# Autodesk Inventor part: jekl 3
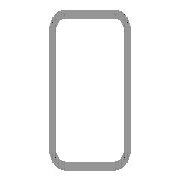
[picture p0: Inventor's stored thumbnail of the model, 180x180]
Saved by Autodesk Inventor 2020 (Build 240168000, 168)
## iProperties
Created: 2019-01
Part Number: jekl 3
Material: Ocel
Description: Duté svařované profily tvářené za studena z nelegované a jemnozrnné konstrukční oceli
Document SubType Name: Modeling
Standard: CSN EN 10219-2
Designer: doma
Standards Organization: CSN
Language: cs-CZ
Size Designation: 80 x 40 x 4  - 2000
Categories: <MemberInstance><Categories><Category DisplayName="Konstrukční profily" InternalName="089c4875-fa83-4c05-b084-43b9cc11f5ed" Mnemonic="GRDR"><CategoryParameter D
Stock Number: 80 x 40 x 4
Density: 7.85 g/cm^3
Appearance: Plech
Mass: 1117.7 g
Surface Area: 729.711 cm^2
Volume: 142.382 cm^3
IsCustomPart: 1
G_L: 2000,000 mm
Author: doma
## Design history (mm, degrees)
node "Počáteční rovina"
node "Koncová rovina"
sketch "Náčrt"
  geometry: L1 (-20, -32)-(-20, 32); L2 (-12, 40)-(12, 40); L3 (20, 32)-(20, -32); L4 (12, -40)-(-12, -40); L5 (-12, 36)-(12, 36); L6 (16, 32)-(16, -32); L7 (12, -36)-(-12, -36); L8 (-16, -32)-(-16, 32); L9 (0, 58.32)-(0, -58.32) reference; L10 (-30.32, 0)-(30.32, 0) reference; A1 r 8 centre (-12, -32) between (-20, -32) and (-12, -40); A2 r 8 centre (-12, 32) between (-12, 40) and (-20, 32); A3 r 8 centre (12, 32) between (20, 32) and (12, 40); A4 r 8 centre (12, -32) between (12, -40) and (20, -32); A5 r 4 centre (-12, 32) between (-12, 36) and (-16, 32); A6 r 4 centre (12, 32) between (16, 32) and (12, 36); A7 r 4 centre (12, -32) between (12, -36) and (16, -32); A8 r 4 centre (-12, -32) between (-16, -32) and (-12, -36)
  constraints: 16 end point, 16 point on circle, 8 centre point, 8 tangent, 4 parallel, 3 equal radius, 2 perpendicular, 7 other
  dimensions: "d7" = 8 radius of A1 (= G_IR); "d10" = 80 distance between parallel lines of L2 L4 (= G_H); "d11" = 40 distance between parallel lines of L1 L3 (= G_W); "d12" = 4 distance between parallel lines of L3 L6 (= G_T); "d15" = 40 distance between parallel lines of L2 L10 (= 0.5 x d10); "d16" = 20 distance between parallel lines of L9 L3 (= 0.5 x d11)
extrude "Těleso" new body sketch "Náčrt" stored distance "d3" = 1000; taper "d4" = 0 deg
node "Driven Length"
  sketch "Sketch3"
    geometry: L1 (0, 0)-(10, 0) reference
    constraints: 2 end point, 1 horizontal
  workplane "Work Plane3"
  sketch "Sketch4"
    geometry: L1 (-2, 0)-(12, 0) reference; L2 (-2, 2000)-(12, 2000) reference
    dimensions: "d18" = 2000 distance between parallel lines of L1 L2 (derived)
sketch "Náčrt5"
  geometry: L1 (0, -4.863)-(76.863, 72) reference; L2 (80, -38)-(110, -8) reference; L3 (110, -8)-(76.863, 72); L4 (110, -8)-(171.667, -224.069); L5 (171.667, -224.069)-(-147.907, -198.442); L6 (-147.907, -198.442)-(-172.297, 167.434); L7 (-172.297, 167.434)-(76.863, 72); L8 (360, -8)-(360, 197) reference; L9 (360, -8)-(575.249, -273.891); L10 (575.249, -273.891)-(1174.143, -160.587); L11 (1174.143, -160.587)-(1174.143, 498.428); L12 (0, -8)-(1000, -8) reference; L13 (1174.143, 498.428)-(360, 197); 1 further point
  constraints: 18 end point, 1 perpendicular
extrude "Vysunutí2" cut sketch "Náčrt5" extent not by distance; stored distance "d19" = 0; taper "d20" = 0 deg
sketch "Náčrt6"
  geometry: L1 (179.823, 113)-(179.823, -134.483); L2 (179.823, -134.483)-(335.914, -140.464); L3 (335.914, -140.464)-(362.402, 174.832); L4 (362.402, 174.832)-(179.823, 113); 1 further point
  constraints: 8 end point
extrude "Vysunutí3" cut sketch "Náčrt6" extent not by distance; stored distance "d22" = 0; taper "d23" = 0 deg
body "Solid1"
node "Referenční1"
node "Referenční2"
node "Referenční3"
other parameters: "G_W" = 40 [user parameter; used in 1 equation term], "G_H" = 80 [user parameter; used in 1 equation term], "G_T" = 4 [user parameter; used in 1 equation term], "G_IR" = 8 [user parameter; used in 1 equation term], "G_L" = 2000 (= d18) [user parameter], "G_OFFSET_START" = 0 [user parameter; used in 1 equation term], "G_OFFSET_END" = 0 [user parameter; used in 1 equation term], "d13" = 0 (computed from G_OFFSET_START), "d17" = 90 deg
